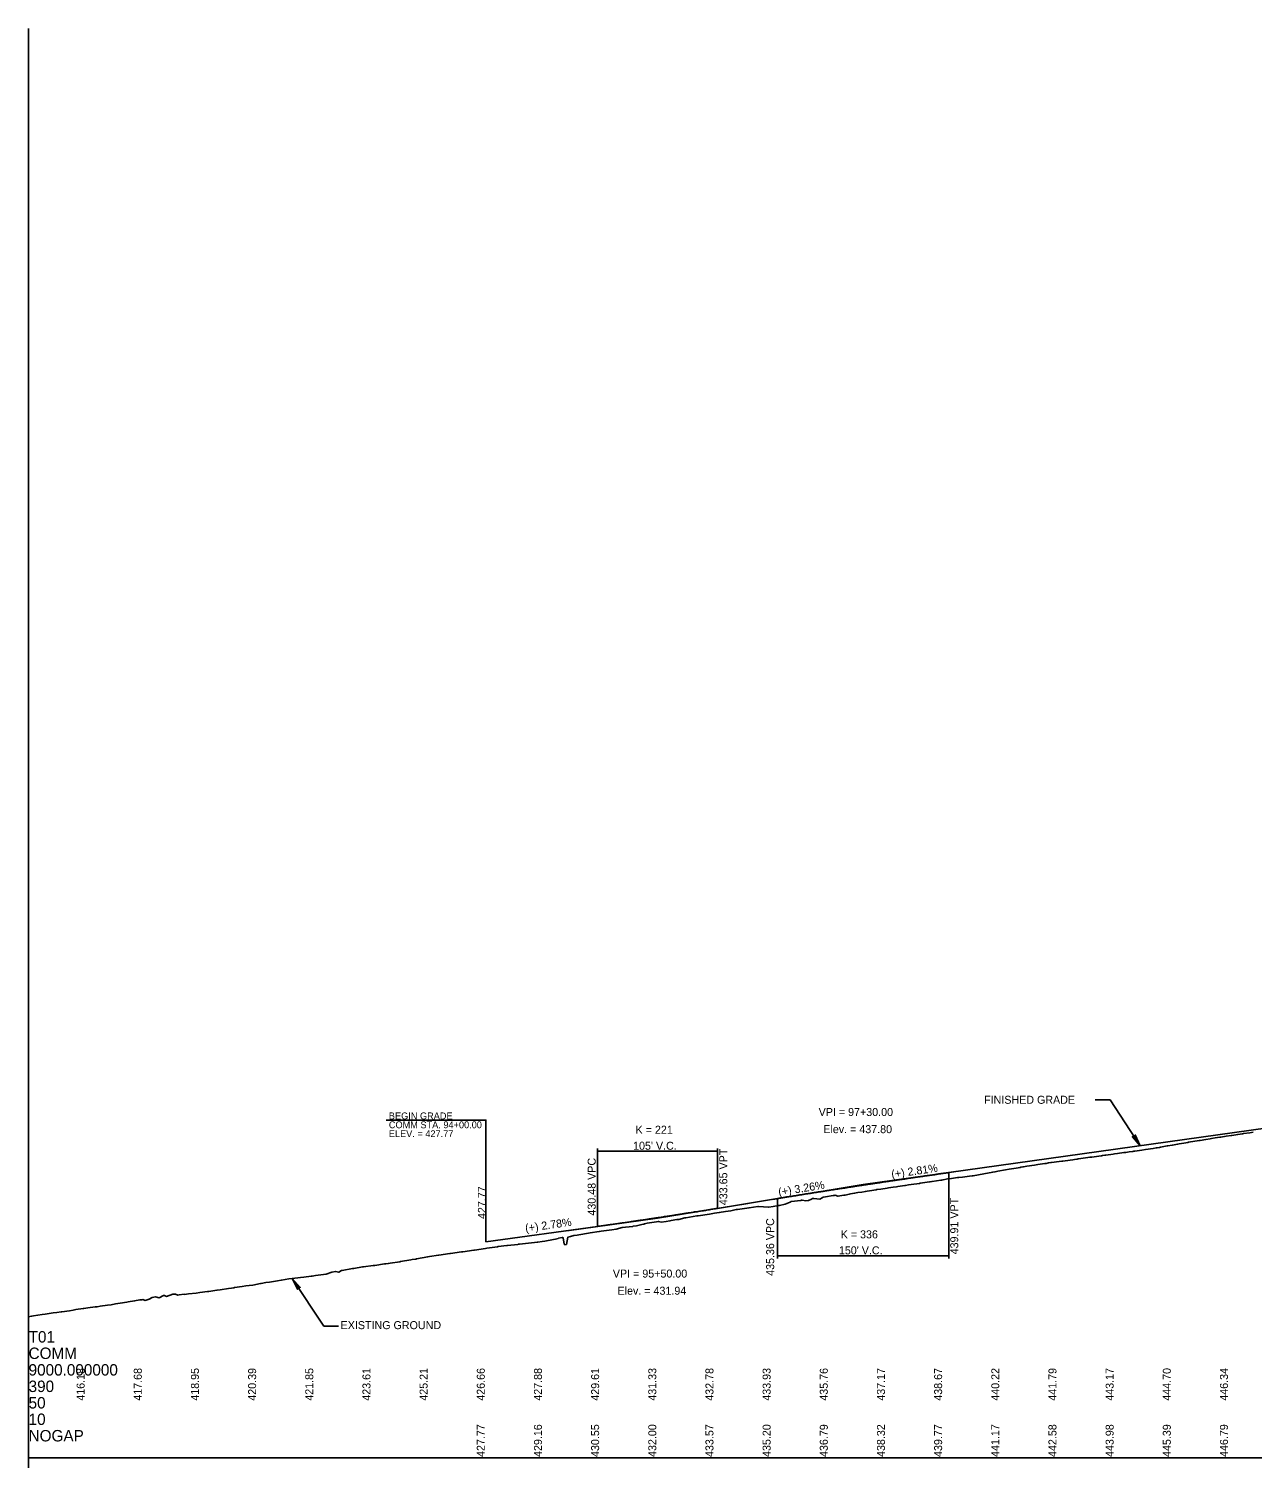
# Model space of a CAD drawing. Extents: x 2017200 to 2047700, y 854850 to 893350.
# Drawn here: x 2020500 to 2021570, y 862100 to 863350 of the extents above; entities that cross this region are included whole.
import ezdxf

# ---------------------------------------------------------------- set-up
doc = ezdxf.new("R2010")
doc.units = 0
for name, color, linetype in [('RD_DDB_GradeTX', 7, 'Continuous'), ('RD_DDB_Profile_EX', 7, 'Continuous'), ('RD_DDB_Profile_Lbl', 7, 'Continuous'), ('RD_DDB_Profile_PR', 7, 'Continuous'), ('RD_DDB_StripGrade', 7, 'Continuous'), ('RD_DDB_VCLbl', 7, 'Continuous'), ('RD_GPK_Profile_Cell', 7, 'Continuous')]:
    doc.layers.add(name, color=color, linetype=linetype)

msp = doc.modelspace()

# ---------------------------------------------------------------- linework, layer by layer
at = {"layer": 'RD_DDB_GradeTX'}
for p, q in [((2021309.2, 862350.1), (2021230, 862339)), ((2021151, 862326.1), (2021230, 862339)), ((2021129, 862322.6), (2021050, 862309.7)), ((2020970.8, 862298.7), (2021050, 862309.7))]:
    msp.add_line(p, q, dxfattribs=at)
at = {"layer": 'RD_DDB_Profile_EX'}
msp.add_lwpolyline([(2020500, 862223.5), (2020502.6, 862223.9), (2020504.3, 862224.2), (2020511.9, 862225.4), (2020514.4, 862225.8), (2020521.5, 862226.9), (2020524.6, 862227.1), (2020528.5, 862227.7), (2020529.1, 862227.7), (2020535.7, 862228.7), (2020539.1, 862229.3), (2020541.3, 862229.7), (2020547.7, 862230.6), (2020548.2, 862230.7), (2020551.9, 862231.1), (2020558.1, 862232), (2020560.1, 862232.2), (2020562.7, 862232.7), (2020569, 862233.6), (2020572.1, 862234), (2020575.9, 862234.6), (2020580, 862235.3), (2020585.9, 862236.2), (2020587.2, 862236.4), (2020592.7, 862237.3), (2020597.2, 862238.1), (2020598.9, 862238.3), (2020599.8, 862238.5), (2020602.1, 862237.8), (2020605.5, 862238.7), (2020608.2, 862240.4), (2020611.1, 862240.9), (2020614.2, 862240.1), (2020617.9, 862241.9), (2020619, 862242.1), (2020620.6, 862241.2), (2020626.2, 862243.1), (2020628.6, 862243.3), (2020630.6, 862242.4), (2020631.8, 862242.7), (2020636, 862243.1), (2020636.5, 862243), (2020639.9, 862243.5), (2020646.5, 862244.2), (2020649.7, 862244.7), (2020656.5, 862245.4), (2020657.6, 862245.6), (2020664.7, 862246.6), (2020667.6, 862247.1), (2020674.7, 862248.1), (2020677.6, 862248.5), (2020679.5, 862248.8), (2020680, 862248.9), (2020686.9, 862250), (2020690, 862250.4), (2020692.8, 862250.8), (2020696, 862251.2), (2020702.8, 862252.4), (2020703.4, 862252.5), (2020707.6, 862253.3), (2020710.8, 862253.8), (2020717.7, 862254.9), (2020720.8, 862255.4), (2020721.3, 862255.5), (2020727.6, 862256.5), (2020730.6, 862257), (2020737.7, 862257.8), (2020740.6, 862258.2), (2020747.1, 862258.9), (2020748, 862259), (2020750.9, 862259.4), (2020758, 862260.4), (2020760.3, 862260.7), (2020765.1, 862262.5), (2020768.4, 862263.1), (2020771.3, 862262.4), (2020773.7, 862263.8), (2020774.4, 862263.9), (2020783.3, 862265.5), (2020784.4, 862265.6), (2020792.1, 862267), (2020792.8, 862267), (2020801.5, 862268.3), (2020802.8, 862268.4), (2020811.3, 862269.6), (2020812.4, 862269.6), (2020814.6, 862269.9), (2020816.2, 862270.2), (2020824.7, 862271.6), (2020825.4, 862271.7), (2020834.2, 862273.1), (2020835.4, 862273.4), (2020838.8, 862273.9), (2020839.3, 862274.1), (2020849.1, 862275.9), (2020850.5, 862276.1), (2020858.5, 862277.3), (2020858.9, 862277.4), (2020868.5, 862278.7), (2020868.9, 862278.8), (2020878.6, 862280.2), (2020879.5, 862280.3), (2020879.8, 862280.3), (2020889.5, 862281.8), (2020890, 862281.8), (2020899.5, 862283.2), (2020900.7, 862283.4), (2020910.1, 862284.7), (2020910.7, 862284.8), (2020918.3, 862285.8), (2020918.8, 862285.9), (2020927.8, 862286.7), (2020928.3, 862286.8), (2020929.5, 862286.9), (2020934.7, 862287.4), (2020942.6, 862288.4), (2020944.8, 862288.7), (2020945.3, 862288.8), (2020949.1, 862289.3), (2020951.5, 862289.6), (2020959.1, 862291.1), (2020960.8, 862291.4), (2020963.1, 862291.9), (2020963.5, 862292.1), (2020966.6, 862292.7), (2020967, 862292.7), (2020967.5, 862292.5), (2020968.3, 862287), (2020969.1, 862286.4), (2020970.4, 862286.7), (2020971.5, 862292.9), (2020974.1, 862293.7), (2020977, 862294.5), (2020979.7, 862294.9), (2020981.4, 862295.2), (2020989.7, 862296.5), (2020991.1, 862296.7), (2020999.1, 862297.9), (2021000.9, 862298.2), (2021003.2, 862298.5), (2021010, 862299.5), (2021014, 862300.1), (2021019.1, 862301.4), (2021028.2, 862302.4), (2021028.5, 862302.4), (2021028.9, 862302.6), (2021031.6, 862303.1), (2021036.5, 862304.2), (2021038.1, 862304.5), (2021038.7, 862304.7), (2021041.1, 862305.2), (2021049.1, 862306.5), (2021050.7, 862306.8), (2021051, 862306.8), (2021053.3, 862306.2), (2021057.6, 862306.8), (2021060.9, 862307.3), (2021061.9, 862307.5), (2021067, 862308.4), (2021068.8, 862308.6), (2021074, 862309.9), (2021074.7, 862310), (2021084.5, 862311.6), (2021085.6, 862311.7), (2021095.4, 862313.2), (2021100, 862313.9), (2021101.9, 862314.2), (2021104.1, 862314.5), (2021109.4, 862315.4), (2021114.1, 862316.2), (2021118.8, 862317.1), (2021120.1, 862317.3), (2021128.3, 862318.5), (2021129.8, 862318.7), (2021130.2, 862318.7), (2021137.8, 862319.8), (2021138.4, 862319.9), (2021147.1, 862319.3), (2021147.5, 862319.3), (2021151.3, 862319.9), (2021156, 862320.6), (2021156.7, 862320.8), (2021161.7, 862321.9), (2021166, 862323.6), (2021167.1, 862324.1), (2021175.4, 862325.2), (2021176.1, 862325.3), (2021176.7, 862325.4), (2021179.9, 862324.8), (2021182.1, 862325.1), (2021184.8, 862326.4), (2021185.7, 862326.9), (2021186.9, 862327), (2021192.1, 862326.3), (2021194.2, 862327.5), (2021195.1, 862328), (2021196.9, 862328.2), (2021203.6, 862329.4), (2021204.5, 862329.6), (2021205.4, 862329.7), (2021207.9, 862328.8), (2021213.1, 862329.7), (2021214.1, 862329.9), (2021217.8, 862330.6), (2021219, 862330.9), (2021222.5, 862331.5), (2021225.3, 862332), (2021228.9, 862332.5), (2021231.9, 862333.1), (2021233.3, 862333.3), (2021235.5, 862333.6), (2021241.3, 862334.5), (2021242, 862334.6), (2021245.3, 862335.1), (2021250.8, 862335.9), (2021252.1, 862336.2), (2021254, 862336.4), (2021256.3, 862336.8), (2021259.2, 862337.2), (2021260.2, 862337.3), (2021266.3, 862338.2), (2021266.9, 862338.3), (2021269.6, 862338.7), (2021274.4, 862339.4), (2021276.9, 862339.8), (2021279.3, 862340.1), (2021279.9, 862340.2), (2021287.9, 862341.4), (2021288.4, 862341.5), (2021289.9, 862341.7), (2021290.3, 862341.8), (2021297.9, 862342.9), (2021298.7, 862343), (2021299.9, 862343.3), (2021302.5, 862343.7), (2021303.7, 862344), (2021307.3, 862344.4), (2021312.5, 862345.1), (2021313.5, 862345.2), (2021316.7, 862345.6), (2021322.9, 862346.4), (2021325.3, 862346.7), (2021326.1, 862346.8), (2021335.6, 862348.5), (2021343.3, 862349.9), (2021345, 862350.2), (2021345.4, 862350.3), (2021347.6, 862350.7), (2021354.4, 862351.9), (2021357.7, 862352.5), (2021363.8, 862353.5), (2021367.4, 862354.1), (2021367.7, 862354.2), (2021369.6, 862354.5), (2021370.1, 862354.6), (2021373.2, 862355.1), (2021379.8, 862356.1), (2021382.7, 862356.5), (2021388.9, 862357.5), (2021389.2, 862357.5), (2021389.9, 862357.6), (2021392.1, 862358), (2021394, 862358.2), (2021394.3, 862358.3), (2021394.8, 862358.3), (2021401.5, 862359.2), (2021403.6, 862359.4), (2021404.7, 862359.6), (2021410.9, 862360.5), (2021413.2, 862360.8), (2021414.8, 862361), (2021417.1, 862361.3), (2021418, 862361.5), (2021420.3, 862361.8), (2021426.3, 862362.6), (2021428.2, 862362.9), (2021429.8, 862363.1), (2021436.2, 862364), (2021438.4, 862364.3), (2021439.2, 862364.4), (2021441.4, 862364.7), (2021442.2, 862364.8), (2021448.6, 862365.7), (2021449.8, 862365.8), (2021452.4, 862366.2), (2021458, 862367), (2021459.7, 862367.2), (2021462.5, 862367.6), (2021465.7, 862368), (2021466.7, 862368.2), (2021467.5, 862368.3), (2021473.7, 862369.2), (2021476.9, 862369.7), (2021483.5, 862370.7), (2021486.3, 862371.2), (2021487, 862371.3), (2021489, 862371.6), (2021490.1, 862371.7), (2021495.7, 862372.8), (2021496.4, 862372.9), (2021500.3, 862373.5), (2021505.1, 862374.4), (2021506.2, 862374.6), (2021510.4, 862375.3), (2021513.8, 862375.9), (2021514.6, 862376), (2021519.9, 862376.9), (2021524, 862377.6), (2021524.6, 862377.6), (2021529.7, 862378.5), (2021533.4, 862379.1), (2021534.6, 862379.3), (2021537.8, 862379.8), (2021541.8, 862380.4), (2021542.8, 862380.6), (2021547.3, 862381.3), (2021551.8, 862382), (2021552.3, 862382), (2021557.6, 862382.9), (2021561.8, 862383.5), (2021562.7, 862383.6), (2021568, 862384.4), (2021571.1, 862384.9)], dxfattribs=at)
at = {"layer": 'RD_DDB_Profile_Lbl'}
for p, q in [((2020758.1, 862215.3), (2020730.6, 862257)), ((2020771, 862215.3), (2020758.1, 862215.3))]:
    msp.add_line(p, q, dxfattribs=at)
for points in [[(2021433, 862413.2), (2021445.9, 862413.2), (2021472.3, 862373)], [(2020900, 862288.9), (2020900, 862395.4), (2020812.7, 862395.4)]]:
    msp.add_lwpolyline(points, dxfattribs=at)
for points in [[(2021472.3, 862373), (2021467.9, 862382.5), (2021467.5, 862380.4), (2021465.4, 862380.9)], [(2020730.6, 862257), (2020735.1, 862247.5), (2020735.5, 862249.6), (2020737.6, 862249.1)]]:
    msp.add_lwpolyline(points, close=True, dxfattribs=at)
at = {"layer": 'RD_DDB_Profile_PR'}
for p, q in [((2021305, 862349.5), (2021875, 862429.6)), ((2021102.5, 862318.2), (2021155, 862326.8)), ((2020900, 862288.9), (2020997.5, 862302.4))]:
    msp.add_line(p, q, dxfattribs=at)
for points in [[(2021155, 862326.8), (2021158, 862327.3), (2021161, 862327.8), (2021164, 862328.3), (2021167, 862328.7), (2021170, 862329.2), (2021173, 862329.7), (2021176, 862330.2), (2021179, 862330.7), (2021182, 862331.1), (2021185, 862331.6), (2021188, 862332.1), (2021191, 862332.6), (2021194, 862333), (2021197, 862333.5), (2021200, 862334), (2021203, 862334.4), (2021206, 862334.9), (2021209, 862335.4), (2021212, 862335.8), (2021215, 862336.3), (2021218, 862336.8), (2021221, 862337.2), (2021224, 862337.7), (2021227, 862338.1), (2021230, 862338.6), (2021233, 862339), (2021236, 862339.5), (2021239, 862339.9), (2021242, 862340.4), (2021245, 862340.8), (2021248, 862341.3), (2021251, 862341.7), (2021254, 862342.2), (2021257, 862342.6), (2021260, 862343.1), (2021263, 862343.5), (2021266, 862343.9), (2021269, 862344.4), (2021272, 862344.8), (2021275, 862345.3), (2021278, 862345.7), (2021281, 862346.1), (2021284, 862346.6), (2021287, 862347), (2021290, 862347.4), (2021293, 862347.8), (2021296, 862348.3), (2021299, 862348.7), (2021302, 862349.1), (2021305, 862349.5)], [(2020997.5, 862302.4), (2020999.6, 862302.7), (2021001.7, 862303), (2021003.8, 862303.3), (2021005.9, 862303.6), (2021008, 862303.9), (2021010.1, 862304.2), (2021012.2, 862304.5), (2021014.3, 862304.8), (2021016.4, 862305.1), (2021018.5, 862305.4), (2021020.6, 862305.7), (2021022.7, 862306), (2021024.8, 862306.3), (2021026.9, 862306.6), (2021029, 862306.9), (2021031.1, 862307.2), (2021033.2, 862307.5), (2021035.3, 862307.8), (2021037.4, 862308.1), (2021039.5, 862308.4), (2021041.6, 862308.8), (2021043.7, 862309.1), (2021045.8, 862309.4), (2021047.9, 862309.7), (2021050, 862310), (2021052.1, 862310.3), (2021054.2, 862310.6), (2021056.3, 862311), (2021058.4, 862311.3), (2021060.5, 862311.6), (2021062.6, 862311.9), (2021064.7, 862312.3), (2021066.8, 862312.6), (2021068.9, 862312.9), (2021071, 862313.2), (2021073.1, 862313.6), (2021075.2, 862313.9), (2021077.3, 862314.2), (2021079.4, 862314.5), (2021081.5, 862314.9), (2021083.6, 862315.2), (2021085.7, 862315.5), (2021087.8, 862315.9), (2021089.9, 862316.2), (2021092, 862316.5), (2021094.1, 862316.9), (2021096.2, 862317.2), (2021098.3, 862317.6), (2021100.4, 862317.9), (2021102.5, 862318.2)]]:
    msp.add_spline(points, degree=3, dxfattribs=at)
at = {"layer": 'RD_DDB_VCLbl'}
for p, q in [((2020997.5, 862370.7), (2020997.5, 862302.4)), ((2020997.5, 862368.2), (2021102.5, 862368.2)), ((2021102.5, 862370.7), (2021102.5, 862318.2)), ((2021305, 862274.3), (2021305, 862349.5)), ((2021155, 862274.3), (2021155, 862326.8)), ((2021155, 862276.8), (2021305, 862276.8))]:
    msp.add_line(p, q, dxfattribs=at)
at = {"layer": 'RD_GPK_Profile_Cell'}
for q in [(2020500, 863350), (2024800, 862100), (2020500, 860850)]:
    msp.add_line((2020500, 862100), q, dxfattribs=at)

# ---------------------------------------------------------------- texts
at = {"layer": 'RD_DDB_GradeTX'}
for s, rotation, p in [('(+) 2.81%', 7.9971, (2021255.1, 862344.6)), ('(+) 3.26%', 9.2454, (2021156.3, 862329)), ('(+) 2.78%', 7.9134, (2020934.8, 862297.4))]:
    msp.add_text(s, height=7, rotation=rotation, dxfattribs=at).set_placement(p)
at = {"layer": 'RD_DDB_Profile_Lbl'}
for s, height, p in [('FINISHED GRADE', 7, (2021335.7, 862409.7)), ('VPI = 97+30.00', 7, (2021191, 862399)), ('COMM STA. 94+00.00', 6, (2020815.1, 862388.3)), ('BEGIN GRADE', 6, (2020815.1, 862396.1)), ('Elev. = 437.80', 7, (2021195.1, 862384)), ('ELEV. = 427.77', 6, (2020815.1, 862380.5)), ('VPI = 95+50.00', 7, (2021011, 862257.7)), ('Elev. = 431.94', 7, (2021015.1, 862242.7)), ('EXISTING GROUND', 7, (2020772.9, 862212.6))]:
    msp.add_text(s, height=height, dxfattribs=at).set_placement(p)
msp.add_text('427.77', height=7, rotation=90, dxfattribs=at).set_placement((2020900, 862308.9))
at = {"layer": 'RD_DDB_StripGrade'}
for s, p in [('433.65 VPT', (2021111.1, 862321)), ('430.48 VPC', (2020996, 862311.9)), ('439.91 VPT', (2021313.1, 862278)), ('435.36 VPC', (2021152.1, 862259.2)), ('416.18', (2020549, 862150)), ('417.68', (2020599, 862150)), ('418.95', (2020649, 862150)), ('420.39', (2020699, 862150)), ('421.85', (2020749, 862150)), ('423.61', (2020799, 862150)), ('425.21', (2020849, 862150)), ('426.66', (2020899, 862150)), ('427.88', (2020949, 862150)), ('429.61', (2020999, 862150)), ('431.33', (2021049, 862150)), ('432.78', (2021099, 862150)), ('433.93', (2021149, 862150)), ('435.76', (2021199, 862150)), ('437.17', (2021249, 862150)), ('438.67', (2021299, 862150)), ('440.22', (2021349, 862150)), ('441.79', (2021399, 862150)), ('443.17', (2021449, 862150)), ('444.70', (2021499, 862150)), ('446.34', (2021549, 862150)), ('427.77', (2020899, 862100.8)), ('429.16', (2020949, 862100.8)), ('430.55', (2020999, 862100.8)), ('432.00', (2021049, 862100.8)), ('433.57', (2021099, 862100.8)), ('435.20', (2021149, 862100.8)), ('436.79', (2021199, 862100.8)), ('438.32', (2021249, 862100.8)), ('439.77', (2021299, 862100.8)), ('441.17', (2021349, 862100.8)), ('442.58', (2021399, 862100.8)), ('443.98', (2021449, 862100.8)), ('445.39', (2021499, 862100.8)), ('446.79', (2021549, 862100.8))]:
    msp.add_text(s, height=7, rotation=90, dxfattribs=at).set_placement(p)
at = {"layer": 'RD_DDB_VCLbl'}
for s, p in [('K = 221', (2021030.9, 862383.5)), ("105' V.C.", (2021028.7, 862369.5)), ('K = 336', (2021210.3, 862292)), ("150' V.C.", (2021208.7, 862278))]:
    msp.add_text(s, height=7, dxfattribs=at).set_placement(p)
at = {"layer": 'RD_GPK_Profile_Cell'}
for s, p in [('T01', (2020500, 862200.9)), ('COMM', (2020500, 862186.5)), ('9000.000000', (2020500, 862172)), ('390', (2020500, 862157.6)), ('50', (2020500, 862143.2)), ('10', (2020500, 862128.8)), ('NOGAP', (2020500, 862114.4))]:
    msp.add_text(s, height=10, dxfattribs=at).set_placement(p)

doc.saveas('drawing.dxf')
